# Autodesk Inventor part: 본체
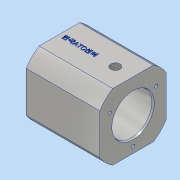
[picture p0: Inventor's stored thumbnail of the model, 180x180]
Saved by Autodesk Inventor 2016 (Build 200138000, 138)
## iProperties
Created: 2020-02
Part Number: 본체
Material: 알루미늄 6061
Document SubType Name: Modeling
Designer: Administrator
Density: 2.7 g/cm^3
Appearance: 알루미늄 - 평지
Mass: 537.891 g
Surface Area: 342.742 cm^2
Volume: 199.219 cm^3
Author: Administrator
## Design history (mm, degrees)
sketch "스케치1"
  geometry: C1 r 37.5 at (0, 0); 1 further point
  constraints: 1 centre point, 1 coincident
  dimensions: "d0" = 75 diameter of C1
extrude "돌출1" new body sketch "스케치1" distance "d1" = 71; taper "d2" = 0 deg
sketch "스케치2"
  geometry: L1 (32, -32)-(-32, -32); L2 (-32, -32)-(-32, 32); L3 (-32, 32)-(32, 32); L4 (32, 32)-(32, -32); L5 (32, -32)-(-32, 32); L6 (-32, -32)-(32, 32); L7 (32, 32)-(-32, 32); L8 (-32, 32)-(-32, 47); L9 (-32, 47)-(32, 47); L10 (32, 47)-(32, 32); L11 (-32, -32)-(-47, -32); L12 (-47, -32)-(-47, 32); L13 (-47, 32)-(-32, 32); L14 (-32, 32)-(-32, -32); L15 (-32, -32)-(32, -32); L16 (32, -32)-(32, -47); L17 (32, -47)-(-32, -47); L18 (-32, -47)-(-32, -32); L19 (32, -32)-(47, -32); L20 (47, -32)-(47, 32); L21 (47, 32)-(32, 32); L22 (32, 32)-(32, -32); 1 further point
  constraints: 44 end point, 10 parallel, 5 horizontal, 5 perpendicular, 4 point on line, 2 midpoint
  dimensions: "d3" = 64 distance of L2.end L3.end; "d4" = 64 distance of L1.end L2.end; "d5" = 15 distance of L7.end L8.end; "d6" = 15 distance of L12.end L13.end; "d7" = 15 distance of L15.end L16.end; "d8" = 15 distance of L21.end L20.end
extrude "돌출2" cut sketch "스케치2" stored distance "d9" = 71; taper "d10" = 0 deg
sketch "스케치3"
  geometry: C1 r 14 at (0, 0); 1 further point
  constraints: 1 centre point, 1 coincident
  dimensions: "d11" = 28 diameter of C1
extrude "돌출3" join sketch "스케치3" distance "d12" = 12; taper "d13" = 0 deg
chamfer "모따기1" distance "d14" = 1; stored, may be unused: second distance "d15" = 2, angle "d16" = 45 deg
sketch "스케치4"
  geometry: C1 r 20 at (0, 0); 1 further point
  constraints: 1 centre point, 1 coincident
  dimensions: "d17" = 40 diameter of C1
extrude "돌출4" cut sketch "스케치4" distance "d18" = 62; taper "d19" = 0 deg
sketch "스케치5"
  geometry: 2 further points
  constraints: 1 coincident
hole "구멍1" sketch "스케치5" at (0, 0) diameter "d20" = 8.917; stored, may be unused: countersink angle "d24" = 90 deg, drill point angle "d26" = 118 deg; dims "d21" = 14, "d22" = 4, "d23" = 2, "d25" = 17
sketch "스케치6"
  geometry: C1 r 2 at (0, 0); 1 further point
  constraints: 1 centre point, 1 coincident
  dimensions: "d27" = 4 diameter of C1
extrude "돌출5" cut sketch "스케치6" distance "d28" = 62; taper "d29" = 0 deg
sketch "스케치7" dims "d30" = 52
  geometry: L1 (0, 0)-(0, -26); C1 r 2 at (0, 0) reference; 3 further points
  constraints: 2 coincident, 2 end point, 1 vertical, 1 vertical alignment, 2 other
hole "구멍2" sketch "스케치7" at (0, -26) diameter "d31" = 3.242; stored, may be unused: countersink angle "d35" = 90 deg, drill point angle "d37" = 118 deg; dims "d32" = 10, "d33" = 4, "d34" = 2, "d36" = 12
sketch "스케치8" dims "d41" = 52
  geometry: L1 (0, 0)-(13, -22.517); L2 (0, 0)-(26, 0); C1 r 2 at (0, 0) reference; 3 further points
  constraints: 4 end point, 2 coincident, 1 equal length, 1 horizontal, 3 other
  dimensions: "d42" = 60 deg angle of L1 L2
hole "구멍4" sketch "스케치8" at (13, -22.517) diameter "d53" = 3.242; stored, may be unused: countersink angle "d57" = 90 deg, drill point angle "d59" = 118 deg; dims "d54" = 10, "d55" = 4, "d56" = 2, "d58" = 12
sketch "스케치10"
  geometry: L1 (-71, 19.551)-(-54, 19.551); 1 further point
  constraints: 2 end point, 1 coincident, 1 horizontal
  dimensions: "d63" = 17 distance of L1.start L1.end
hole "구멍5" sketch "스케치10" at (-54, 19.551) diameter "d64" = 8.917; stored, may be unused: countersink angle "d68" = 90 deg, drill point angle "d70" = 118 deg; dims "d65" = 6, "d66" = 4, "d67" = 2, "d69" = 9
sketch "스케치11"
  geometry: C1 r 4.458 at (-54, 19.551) reference; 2 further points
  constraints: 1 coincident
hole "구멍6" sketch "스케치11" at (-54, 19.551) diameter "d71" = 4; stored, may be unused: countersink angle "d75" = 90 deg, drill point angle "d77" = 118 deg; dims "d72" = 6, "d73" = 4, "d74" = 2, "d76" = 20
sketch "스케치12"
  geometry: L1 (-71, 19.551)-(0, 19.551); L2 (0, 0)-(0, 39.102) reference; 1 further point
  constraints: 2 end point, 1 midpoint, 1 other
  dimensions: "d78" = 20 distance from line of L2 point (-20, 19.551); "d79" = 0 distance from line of L1 point (-20, 19.551)
feature "엠보싱1" sketch "스케치12" dims "d3" = 64, "d4" = 64, "d5" = 15, "d6" = 15, "d7" = 15, "d8" = 15, "d80" = 0.5, "d81" = 0
chamfer "모따기2" distance "d82" = 1.8; stored, may be unused: second distance "d83" = 2, angle "d84" = 15 deg
node "솔리드1"
pattern_circular "원형 패턴1" dims angle "d39" = 360 deg
pattern_circular "원형 패턴3" dims angle "d61" = 360 deg
